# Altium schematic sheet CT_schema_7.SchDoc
size 221 x 258 mm
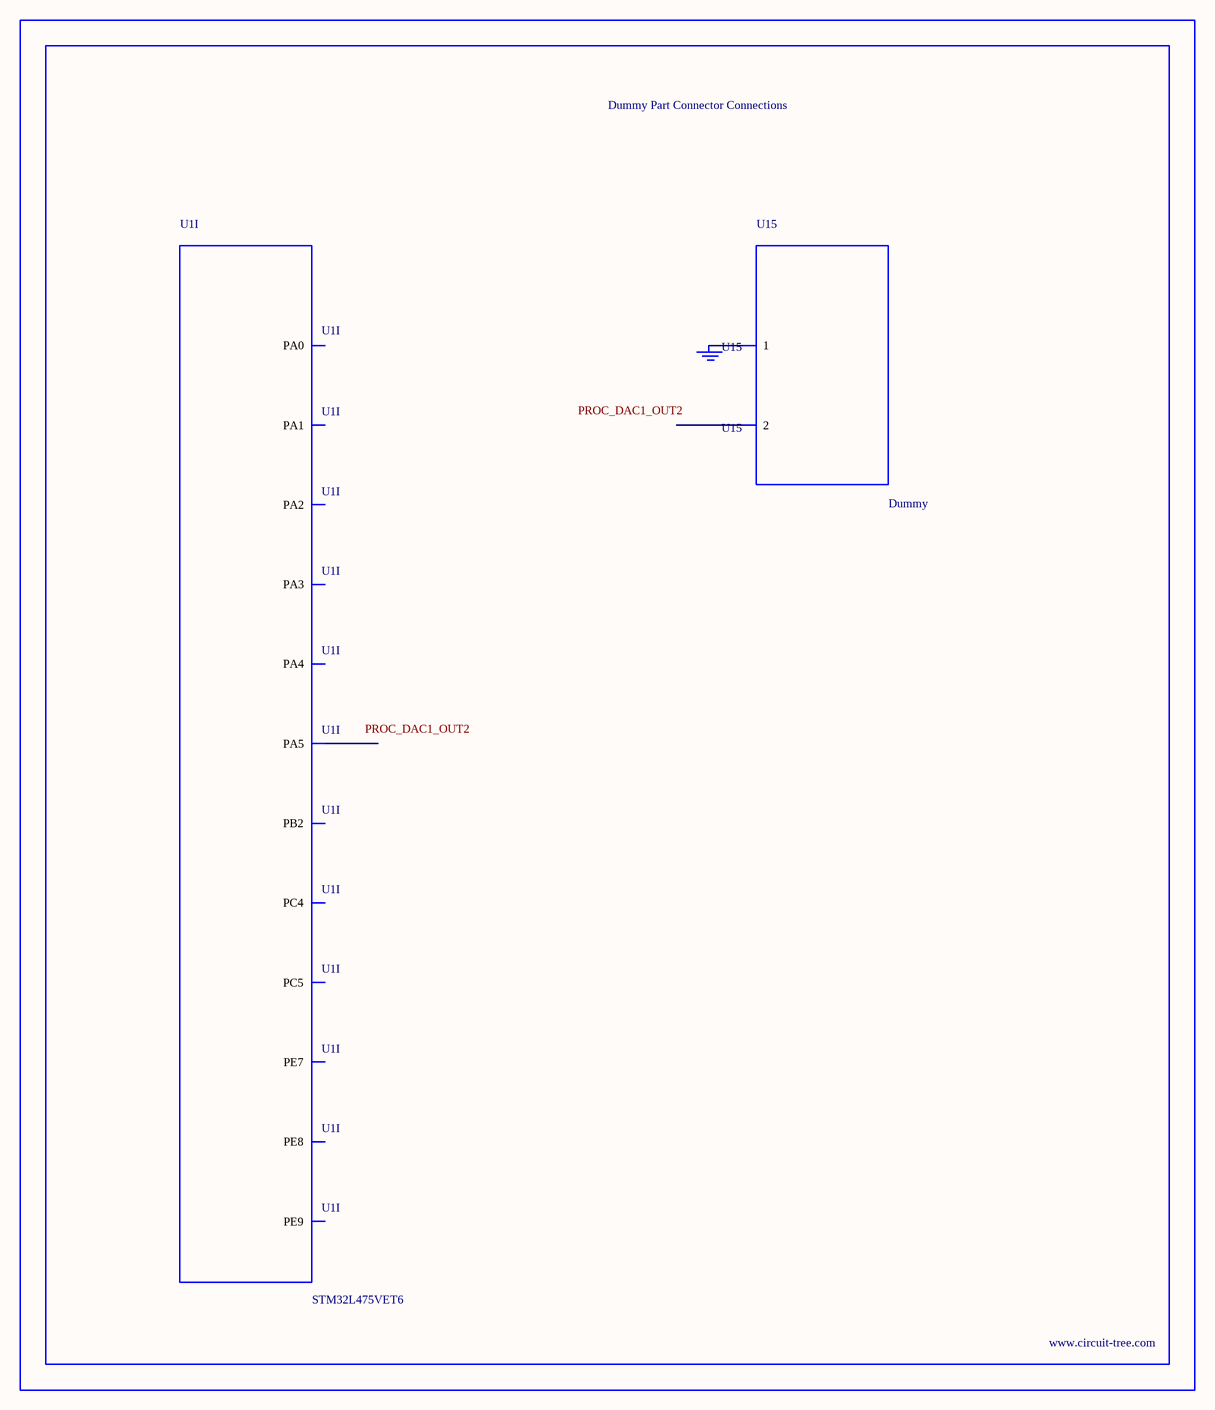
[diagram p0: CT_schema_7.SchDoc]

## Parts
BORDER6  (no value)
GND_INSTANCE_6_0  (no value)
U1  STM32L475VET6  [LQFP100]  (part I of 9)
U15  Dummy  [DUMMY_PACKAGE_160]

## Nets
NetGND_INSTANCE_6_0_0: GND_INSTANCE_6_0.0(GND) U15.1

Not connected (* = marked no-connect by the designer): U1 23(PA0) 24(PA1) 25(PA2) 26(PA3) 29(PA4) 30(PA5) 33(PC4) 34(PC5) 37(PB2) 38(PE7) 39(PE8) 40(PE9); U15 2

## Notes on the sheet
- Labels drawn without touching a wire or pin: PROC_DAC1_OUT2

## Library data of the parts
BORDER6 = BORDER_PAGE6
GND_INSTANCE_6_0 = GND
